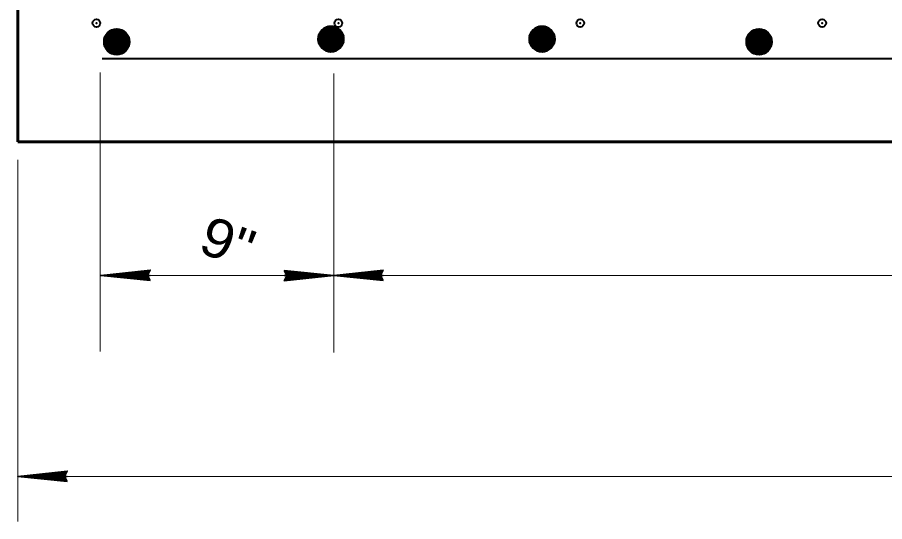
# Model space of a CAD drawing. Extents: x 14.14 to 17.34, y -1.61 to 0.38.
# Drawn here: x 15.9996 to 16.1851, y -0.0965 to 0.0114 of the extents above; entities that cross this region are included whole.
import ezdxf
from ezdxf.enums import TextEntityAlignment as Align

# ---------------------------------------------------------------- set-up
doc = ezdxf.new("R2010")
doc.units = 0
doc.header["$LTSCALE"] = 0.0033
doc.header["$PDMODE"] = 32
doc.header["$PDSIZE"] = 0.00165
doc.layers.add('1', color=7, linetype='Continuous', lineweight=40)

msp = doc.modelspace()

# ---------------------------------------------------------------- linework, layer by layer
at = {"layer": '1', "lineweight": 60}
for p, q in [((15.999667, -0.01525), (15.999667, 0.068083)), ((16.019, 0.00775), (16.018833, 0.004833)), ((16.01925, 0.00775), (16.019, 0.004833)), ((16.019417, 0.00775), (16.01925, 0.00475)), ((16.019583, 0.00775), (16.019333, 0.00475)), ((16.01975, 0.00775), (16.019583, 0.00475)), ((16.02, 0.00775), (16.019833, 0.00475)), ((16.02025, 0.00775), (16.02, 0.00475)), ((16.020333, 0.007667), (16.020167, 0.00475)), ((16.0205, 0.007667), (16.020333, 0.00475)), ((16.020667, 0.007667), (16.0205, 0.00475)), ((16.020917, 0.007667), (16.020667, 0.00475)), ((16.021083, 0.007667), (16.020917, 0.00475)), ((16.021333, 0.007583), (16.021083, 0.004667)), ((16.021583, 0.007583), (16.021333, 0.004667)), ((16.02175, 0.007583), (16.021583, 0.004667)), ((16.021833, 0.007583), (16.021667, 0.004667)), ((16.022, 0.007583), (16.021833, 0.004667)), ((16.022083, 0.007583), (16.021917, 0.004667)), ((16.022333, 0.0075), (16.022083, 0.004583)), ((16.0225, 0.0075), (16.022333, 0.004583)), ((16.022667, 0.0075), (16.022417, 0.004583)), ((16.022833, 0.0075), (16.022667, 0.004583)), ((16.023083, 0.0075), (16.022917, 0.004583)), ((16.064833, 0.008333), (16.064667, 0.005417)), ((16.065083, 0.008333), (16.064833, 0.005417)), ((16.06525, 0.008333), (16.065083, 0.005333)), ((16.065417, 0.008333), (16.065167, 0.005333)), ((16.065583, 0.008333), (16.065417, 0.005333)), ((16.065833, 0.008333), (16.065667, 0.005333)), ((16.066083, 0.008333), (16.065833, 0.005333)), ((16.066167, 0.00825), (16.066, 0.005333)), ((16.066333, 0.00825), (16.066167, 0.005333)), ((16.0665, 0.00825), (16.066333, 0.005333)), ((16.06675, 0.00825), (16.0665, 0.005333)), ((16.066917, 0.00825), (16.06675, 0.005333)), ((16.067167, 0.008167), (16.066917, 0.00525)), ((16.067417, 0.008167), (16.067167, 0.00525)), ((16.067583, 0.008167), (16.067417, 0.00525)), ((16.067667, 0.008167), (16.0675, 0.00525)), ((16.067833, 0.008167), (16.067667, 0.00525)), ((16.067917, 0.008167), (16.06775, 0.00525)), ((16.068167, 0.008083), (16.067917, 0.005167)), ((16.068333, 0.008083), (16.068167, 0.005167)), ((16.0685, 0.008083), (16.06825, 0.005167)), ((16.068667, 0.008083), (16.0685, 0.005167)), ((16.068917, 0.008083), (16.06875, 0.005167)), ((16.069167, 0.006167), (16.069, 0.008)), ((16.11, 0.008333), (16.109833, 0.005417)), ((16.11025, 0.008333), (16.11, 0.005417)), ((16.110417, 0.008333), (16.11025, 0.005333)), ((16.110583, 0.008333), (16.110333, 0.005333)), ((16.11075, 0.008333), (16.110583, 0.005333)), ((16.111, 0.008333), (16.110833, 0.005333)), ((16.11125, 0.008333), (16.111, 0.005333)), ((16.111333, 0.00825), (16.111167, 0.005333)), ((16.1115, 0.00825), (16.111333, 0.005333)), ((16.111667, 0.00825), (16.1115, 0.005333)), ((16.111917, 0.00825), (16.111667, 0.005333)), ((16.112083, 0.00825), (16.111917, 0.005333)), ((16.112333, 0.008167), (16.112083, 0.00525)), ((16.112583, 0.008167), (16.112333, 0.00525)), ((16.11275, 0.008167), (16.112583, 0.00525)), ((16.112833, 0.008167), (16.112667, 0.00525)), ((16.113, 0.008167), (16.112833, 0.00525)), ((16.113083, 0.008167), (16.112917, 0.00525)), ((16.113333, 0.008083), (16.113083, 0.005167)), ((16.1135, 0.008083), (16.113333, 0.005167)), ((16.113667, 0.008083), (16.113417, 0.005167)), ((16.113833, 0.008083), (16.113667, 0.005167)), ((16.114083, 0.008083), (16.113917, 0.005167)), ((16.114333, 0.006167), (16.114167, 0.008)), ((16.156417, 0.00775), (16.15625, 0.004833)), ((16.156667, 0.00775), (16.156417, 0.004833)), ((16.156833, 0.00775), (16.156667, 0.00475)), ((16.157, 0.00775), (16.15675, 0.00475)), ((16.157167, 0.00775), (16.157, 0.00475)), ((16.157417, 0.00775), (16.15725, 0.00475)), ((16.157667, 0.00775), (16.157417, 0.00475)), ((16.15775, 0.007667), (16.157583, 0.00475)), ((16.157917, 0.007667), (16.15775, 0.00475)), ((16.158083, 0.007667), (16.157917, 0.00475)), ((16.158333, 0.007667), (16.158083, 0.00475)), ((16.1585, 0.007667), (16.158333, 0.00475)), ((16.15875, 0.007583), (16.1585, 0.004667)), ((16.159, 0.007583), (16.15875, 0.004667)), ((16.159167, 0.007583), (16.159, 0.004667)), ((16.15925, 0.007583), (16.159083, 0.004667)), ((16.159417, 0.007583), (16.15925, 0.004667)), ((16.1595, 0.007583), (16.159333, 0.004667)), ((16.15975, 0.0075), (16.1595, 0.004583)), ((16.159917, 0.0075), (16.15975, 0.004583)), ((16.160083, 0.0075), (16.159833, 0.004583)), ((16.16025, 0.0075), (16.160083, 0.004583)), ((16.1605, 0.0075), (16.160333, 0.004583)), ((16.023333, 0.005583), (16.018583, 0.004833)), ((16.023333, 0.005583), (16.023167, 0.007417)), ((16.069167, 0.006167), (16.064417, 0.005417)), ((16.114333, 0.006167), (16.109583, 0.005417)), ((16.16075, 0.005583), (16.156, 0.004833)), ((16.16075, 0.005583), (16.160583, 0.007417))]:
    msp.add_line(p, q, dxfattribs=at)
at = {"layer": '1'}
for p, q in [((16.01875, 0.00775), (16.023333, 0.005583)), ((16.019083, 0.00775), (16.023, 0.007083)), ((16.019083, 0.007583), (16.023, 0.006833)), ((16.019167, 0.008083), (16.023, 0.007417)), ((16.021083, 0.00725), (16.022417, 0.00825)), ((16.023167, 0.007417), (16.021917, 0.008583)), ((16.064583, 0.008333), (16.069167, 0.006167)), ((16.064833, 0.007917), (16.06875, 0.007167)), ((16.064833, 0.00775), (16.06875, 0.007)), ((16.064833, 0.0075), (16.068667, 0.00675)), ((16.064917, 0.008333), (16.068833, 0.007667)), ((16.064917, 0.008167), (16.068833, 0.007417)), ((16.065, 0.008667), (16.068833, 0.008)), ((16.066917, 0.007833), (16.06825, 0.008833)), ((16.069, 0.008), (16.06775, 0.009167)), ((16.10975, 0.008333), (16.114333, 0.006167)), ((16.11, 0.007917), (16.113917, 0.007167)), ((16.11, 0.00775), (16.113917, 0.007)), ((16.11, 0.0075), (16.113833, 0.00675)), ((16.110083, 0.008333), (16.114, 0.007667)), ((16.110083, 0.008167), (16.114, 0.007417)), ((16.110167, 0.008667), (16.114, 0.008)), ((16.112083, 0.007833), (16.113417, 0.008833)), ((16.114167, 0.008), (16.112917, 0.009167)), ((16.156167, 0.00775), (16.16075, 0.005583)), ((16.1565, 0.00775), (16.160417, 0.007083)), ((16.1565, 0.007583), (16.160417, 0.006833)), ((16.156583, 0.008083), (16.160417, 0.007417)), ((16.1585, 0.00725), (16.159833, 0.00825)), ((16.160583, 0.007417), (16.159333, 0.008583)), ((16.01875, 0.005917), (16.022667, 0.005167)), ((16.018833, 0.006333), (16.022667, 0.005583)), ((16.018833, 0.006167), (16.022667, 0.005417)), ((16.018917, 0.00675), (16.02275, 0.006083)), ((16.018917, 0.006583), (16.02275, 0.005833)), ((16.019, 0.007333), (16.022917, 0.006583)), ((16.019, 0.007167), (16.022917, 0.006417)), ((16.019, 0.006917), (16.022833, 0.006167)), ((16.064417, 0.005583), (16.06825, 0.004833)), ((16.0645, 0.006083), (16.068417, 0.005333)), ((16.0645, 0.005917), (16.068333, 0.005167)), ((16.0645, 0.005667), (16.068333, 0.005)), ((16.064583, 0.0065), (16.0685, 0.00575)), ((16.064667, 0.006917), (16.0685, 0.006167)), ((16.064667, 0.00675), (16.0685, 0.006)), ((16.06475, 0.007333), (16.068583, 0.006667)), ((16.06475, 0.007167), (16.068583, 0.006417)), ((16.109583, 0.005583), (16.113417, 0.004833)), ((16.109667, 0.006083), (16.113583, 0.005333)), ((16.109667, 0.005917), (16.1135, 0.005167)), ((16.109667, 0.005667), (16.1135, 0.005)), ((16.10975, 0.0065), (16.113667, 0.00575)), ((16.109833, 0.006917), (16.113667, 0.006167)), ((16.109833, 0.00675), (16.113667, 0.006)), ((16.109917, 0.007333), (16.11375, 0.006667)), ((16.109917, 0.007167), (16.11375, 0.006417)), ((16.156167, 0.005917), (16.160083, 0.005167)), ((16.15625, 0.006333), (16.160083, 0.005583)), ((16.15625, 0.006167), (16.160083, 0.005417)), ((16.156333, 0.00675), (16.160167, 0.006083)), ((16.156333, 0.006583), (16.160167, 0.005833)), ((16.156417, 0.007333), (16.160333, 0.006583)), ((16.156417, 0.007167), (16.160333, 0.006417)), ((16.156417, 0.006917), (16.16025, 0.006167)), ((16.018583, 0.005), (16.022417, 0.00425)), ((16.018583, 0.004833), (16.022417, 0.004083)), ((16.018667, 0.0055), (16.022583, 0.00475)), ((16.018667, 0.005333), (16.0225, 0.004583)), ((16.018667, 0.005083), (16.0225, 0.004417)), ((16.022917, 0.004583), (16.019167, 0.004167)), ((16.064417, 0.005417), (16.06825, 0.004667)), ((16.06875, 0.005167), (16.065, 0.00475)), ((16.109583, 0.005417), (16.113417, 0.004667)), ((16.113917, 0.005167), (16.110167, 0.00475)), ((16.156, 0.005), (16.159833, 0.00425)), ((16.156, 0.004833), (16.159833, 0.004083)), ((16.156083, 0.0055), (16.16, 0.00475)), ((16.156083, 0.005333), (16.159917, 0.004583)), ((16.156083, 0.005083), (16.159917, 0.004417)), ((16.160333, 0.004583), (16.156583, 0.004167)), ((16.01775, 0.002583), (16.481833, 0.002583))]:
    msp.add_line(p, q, dxfattribs=at)
at = {"layer": '1', "lineweight": 13}
for p, q in [((16.017333, -0.000417), (16.017333, -0.060083)), ((16.06725, -0.000583), (16.06725, -0.060333)), ((15.999667, -0.019083), (15.999667, -0.0965)), ((16.01775, -0.043833), (16.481833, -0.043833)), ((15.999583, -0.086833), (16.498917, -0.086833))]:
    msp.add_line(p, q, dxfattribs=at)
at = {"layer": '1', "lineweight": 35}
for p, q in [((16.028, -0.043833), (16.017417, -0.043833)), ((16.02775, -0.044667), (16.019917, -0.043667)), ((16.02775, -0.044667), (16.019917, -0.043833)), ((16.02775, -0.044833), (16.019917, -0.043917)), ((16.02775, -0.044833), (16.019917, -0.043917)), ((16.02775, -0.04475), (16.019917, -0.043917)), ((16.02775, -0.04275), (16.020417, -0.043583)), ((16.02775, -0.042917), (16.020417, -0.043667)), ((16.02775, -0.043), (16.020417, -0.043833)), ((16.027833, -0.043167), (16.0205, -0.043917)), ((16.056667, -0.043833), (16.06725, -0.043833)), ((16.056833, -0.0445), (16.064167, -0.04375)), ((16.056917, -0.042833), (16.06475, -0.04375)), ((16.056917, -0.042833), (16.06475, -0.04375)), ((16.056917, -0.042917), (16.06475, -0.04375)), ((16.056917, -0.043), (16.06475, -0.043833)), ((16.056917, -0.043), (16.06475, -0.044)), ((16.056917, -0.044667), (16.06425, -0.043833)), ((16.056917, -0.04475), (16.06425, -0.044)), ((16.056917, -0.044917), (16.06425, -0.044083)), ((16.077833, -0.043833), (16.06725, -0.043833)), ((16.077583, -0.044667), (16.06975, -0.043667)), ((16.077583, -0.044667), (16.06975, -0.043833)), ((16.077583, -0.044833), (16.06975, -0.043917)), ((16.077583, -0.044833), (16.06975, -0.043917)), ((16.077583, -0.04475), (16.06975, -0.043917)), ((16.077583, -0.04275), (16.07025, -0.043583)), ((16.077583, -0.042917), (16.07025, -0.043667)), ((16.077583, -0.043), (16.07025, -0.043833)), ((16.077667, -0.043167), (16.070333, -0.043917)), ((16.01025, -0.086833), (15.999667, -0.086833)), ((16.01, -0.087667), (16.002167, -0.086667)), ((16.01, -0.087667), (16.002167, -0.086833)), ((16.01, -0.087833), (16.002167, -0.086917)), ((16.01, -0.087833), (16.002167, -0.086917)), ((16.01, -0.08775), (16.002167, -0.086917)), ((16.01, -0.08575), (16.002667, -0.086583)), ((16.01, -0.085917), (16.002667, -0.086667)), ((16.01, -0.086), (16.002667, -0.086833)), ((16.010083, -0.086167), (16.00275, -0.086917))]:
    msp.add_line(p, q, dxfattribs=at)
at = {"layer": '1', "lineweight": 60}
for points in [[(15.999667, -0.01525), (16.499667, -0.01525), (16.499667, 0.068083)], [(16.06825, 0.004667), (16.06825, 0.008833), (16.066583, 0.004167), (16.067083, 0.009333), (16.065, 0.00475), (16.06575, 0.00925), (16.067333, 0.00425), (16.064167, 0.007583), (16.069, 0.008), (16.06575, 0.004333), (16.06775, 0.009167), (16.064583, 0.008333), (16.064417, 0.005417)], [(16.065, 0.00475), (16.0665, 0.007), (16.064333, 0.007917), (16.066333, 0.009333), (16.0665, 0.007083), (16.068167, 0.00475), (16.064167, 0.007083), (16.066917, 0.007833)], [(16.113417, 0.004667), (16.113417, 0.008833), (16.11175, 0.004167), (16.11225, 0.009333), (16.110167, 0.00475), (16.110917, 0.00925), (16.1125, 0.00425), (16.109333, 0.007583), (16.114167, 0.008), (16.110917, 0.004333), (16.112917, 0.009167), (16.10975, 0.008333), (16.109583, 0.005417)], [(16.110167, 0.00475), (16.111667, 0.007), (16.1095, 0.007917), (16.1115, 0.009333), (16.111667, 0.007083), (16.113333, 0.00475), (16.109333, 0.007083), (16.112083, 0.007833)], [(16.018167, 0.006083), (16.023333, 0.00675), (16.01875, 0.00775)], [(16.022417, 0.004083), (16.022417, 0.00825), (16.02075, 0.003583), (16.02125, 0.00875), (16.019167, 0.004167), (16.019917, 0.008667), (16.0215, 0.003667), (16.018333, 0.007), (16.023167, 0.007417), (16.019917, 0.00375), (16.021917, 0.008583), (16.01875, 0.00775), (16.018583, 0.004833)], [(16.019167, 0.004167), (16.020667, 0.006417), (16.0185, 0.007333), (16.0205, 0.00875), (16.020667, 0.0065), (16.022333, 0.004167), (16.018333, 0.0065), (16.021083, 0.00725)], [(16.021917, 0.008583), (16.020667, 0.006417), (16.022917, 0.004583)], [(16.064, 0.006667), (16.069167, 0.007333), (16.064583, 0.008333)], [(16.06775, 0.009167), (16.0665, 0.007), (16.06875, 0.005167)], [(16.109167, 0.006667), (16.114333, 0.007333), (16.10975, 0.008333)], [(16.112917, 0.009167), (16.111667, 0.007), (16.113917, 0.005167)], [(16.155583, 0.006083), (16.16075, 0.00675), (16.156167, 0.00775)], [(16.159833, 0.004083), (16.159833, 0.00825), (16.158167, 0.003583), (16.158667, 0.00875), (16.156583, 0.004167), (16.157333, 0.008667), (16.158917, 0.003667), (16.15575, 0.007), (16.160583, 0.007417), (16.157333, 0.00375), (16.159333, 0.008583), (16.156167, 0.00775), (16.156, 0.004833)], [(16.156583, 0.004167), (16.158083, 0.006417), (16.155917, 0.007333), (16.157917, 0.00875), (16.158083, 0.0065), (16.15975, 0.004167), (16.15575, 0.0065), (16.1585, 0.00725)], [(16.159333, 0.008583), (16.158083, 0.006417), (16.160333, 0.004583)]]:
    msp.add_lwpolyline(points, dxfattribs=at)
at = {"layer": '1'}
for points in [[(16.018583, 0.004833), (16.020667, 0.003583), (16.022417, 0.004083), (16.023333, 0.005583)], [(16.064417, 0.005417), (16.0665, 0.004167), (16.06825, 0.004667), (16.069167, 0.006167)], [(16.109583, 0.005417), (16.111667, 0.004167), (16.113417, 0.004667), (16.114333, 0.006167)], [(16.156, 0.004833), (16.158083, 0.003583), (16.159833, 0.004083), (16.16075, 0.005583)]]:
    msp.add_lwpolyline(points, dxfattribs=at)
at = {"layer": '1', "lineweight": 35}
for points in [[(16.028, -0.044917), (16.017417, -0.043833), (16.028, -0.042667), (16.027417, -0.043833)], [(16.077833, -0.044917), (16.06725, -0.043833), (16.077833, -0.042667), (16.07725, -0.043833)], [(16.02725, -0.043917), (16.022583, -0.044), (16.022583, -0.043917), (16.0235, -0.043917), (16.02725, -0.044), (16.02425, -0.044083), (16.027417, -0.044167), (16.025167, -0.04425), (16.027417, -0.044333), (16.023917, -0.044083), (16.01925, -0.043917), (16.020167, -0.043667), (16.018917, -0.043667), (16.02725, -0.043667), (16.024833, -0.0435), (16.027417, -0.0435), (16.022083, -0.043917), (16.027417, -0.04325)], [(16.056667, -0.04275), (16.06725, -0.043833), (16.056667, -0.045), (16.05725, -0.043833)], [(16.057417, -0.04375), (16.062083, -0.043667), (16.062083, -0.04375), (16.061167, -0.04375), (16.057417, -0.043667), (16.060417, -0.043583), (16.05725, -0.0435), (16.0595, -0.043417), (16.05725, -0.043333), (16.06075, -0.043583), (16.065417, -0.04375), (16.0645, -0.044), (16.06575, -0.044), (16.057417, -0.044), (16.059833, -0.044167), (16.05725, -0.044167), (16.062583, -0.04375), (16.05725, -0.044417)], [(16.077083, -0.043917), (16.072417, -0.044), (16.072417, -0.043917), (16.073333, -0.043917), (16.077083, -0.044), (16.074083, -0.044083), (16.07725, -0.044167), (16.075, -0.04425), (16.07725, -0.044333), (16.07375, -0.044083), (16.069083, -0.043917), (16.07, -0.043667), (16.06875, -0.043667), (16.077083, -0.043667), (16.074667, -0.0435), (16.07725, -0.0435), (16.071917, -0.043917), (16.07725, -0.04325)], [(16.01025, -0.087917), (15.999667, -0.086833), (16.01025, -0.085667), (16.009667, -0.086833)], [(16.0095, -0.086917), (16.004833, -0.087), (16.004833, -0.086917), (16.00575, -0.086917), (16.0095, -0.087), (16.0065, -0.087083), (16.009667, -0.087167), (16.007417, -0.08725), (16.009667, -0.087333), (16.006167, -0.087083), (16.0015, -0.086917), (16.002417, -0.086667), (16.001167, -0.086667), (16.0095, -0.086667), (16.007083, -0.0865), (16.009667, -0.0865), (16.004333, -0.086917), (16.009667, -0.08625)]]:
    msp.add_lwpolyline(points, close=True, dxfattribs=at)
for points in [[(16.02725, -0.043917), (16.027667, -0.044667), (16.027417, -0.044417), (16.02725, -0.044083), (16.027, -0.044167), (16.027167, -0.0445), (16.027333, -0.04375), (16.0275, -0.04325), (16.02775, -0.042833)], [(16.057417, -0.04375), (16.057, -0.043), (16.05725, -0.04325), (16.057417, -0.043583), (16.057667, -0.0435), (16.0575, -0.043167), (16.057333, -0.043917), (16.057167, -0.044417), (16.056917, -0.044833)], [(16.077083, -0.043917), (16.0775, -0.044667), (16.07725, -0.044417), (16.077083, -0.044083), (16.076833, -0.044167), (16.077, -0.0445), (16.077167, -0.04375), (16.077333, -0.04325), (16.077583, -0.042833)], [(16.0095, -0.086917), (16.009917, -0.087667), (16.009667, -0.087417), (16.0095, -0.087083), (16.00925, -0.087167), (16.009417, -0.0875), (16.009583, -0.08675), (16.00975, -0.08625), (16.01, -0.085833)]]:
    msp.add_lwpolyline(points, dxfattribs=at)
at = {"layer": '1', "lineweight": 60}
for centre in [(16.066667, 0.006767), (16.111833, 0.006767), (16.020833, 0.006183), (16.15825, 0.006183)]:
    msp.add_circle(centre, 0.00264, dxfattribs=at)
at = {"layer": '1'}
for p in [(16.0165, 0.010167), (16.06825, 0.010167), (16.12, 0.010167), (16.17175, 0.010167), (16.020167, 0.005417), (16.065917, 0.005417), (16.11175, 0.005417), (16.1575, 0.005417)]:
    msp.add_point(p, dxfattribs=at)

# ---------------------------------------------------------------- texts
at = {"layer": '1', "width": 1.1}
msp.add_text('9"', height=0.008334, rotation=340, dxfattribs=at).set_placement((16.043158, -0.04062), align=Align.CENTER)

doc.saveas('drawing.dxf')
